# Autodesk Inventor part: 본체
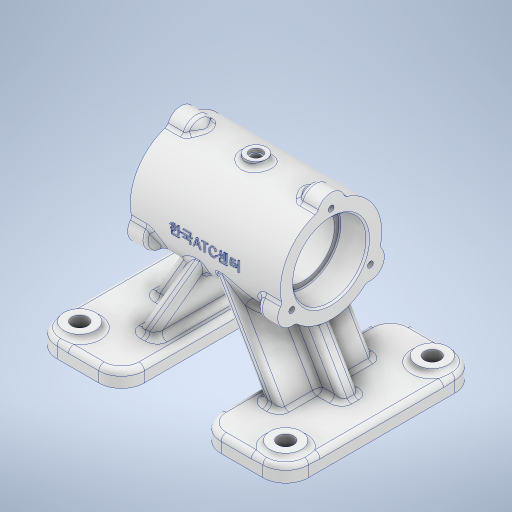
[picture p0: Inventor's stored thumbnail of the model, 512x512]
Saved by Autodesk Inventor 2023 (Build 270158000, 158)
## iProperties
Created: 2026-04
Part Number: 본체
Material: 알루미늄 6061
Document SubType Name: Modeling
Designer: 4강의실
Density: 2.7 g/cm^3
Appearance: 알루미늄 - 평지
Mass: 773.015 g
Surface Area: 685.715 cm^2
Volume: 286.302 cm^3
Author: 4강의실
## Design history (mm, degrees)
sketch "스케치1"
  geometry: L1 (-72, 55)-(72, 55); L2 (72, 55)-(72, -55); L3 (72, -55)-(-72, -55); L4 (-72, -55)-(-72, 55); L5 (-72, 55)-(72, -55); L6 (72, 55)-(-72, -55); L7 (-22, 55)-(22, 55); L8 (22, 55)-(22, -55); L9 (22, -55)-(-22, -55); L10 (-22, -55)-(-22, 55); L11 (-22, 55)-(22, -55); L12 (22, 55)-(-22, -55); 5 further points
  constraints: 24 end point, 4 midpoint, 4 parallel, 2 perpendicular, 1 collinear, 1 horizontal
  dimensions: "d0" = 144 distance of L1.start L1.end; "d1" = 110 distance of L1.end L2.end; "d2" = 44 distance of L7.start L7.end; "d3" = 110 distance of L9.end L7.start
extrude "돌출1" new body sketch "스케치1" distance "d4" = 9; taper "d5" = 0 deg
fillet "모깎기1" dims "d6" = 13
sketch "스케치2"
  geometry: L1 (59, -42)-(-59, -42); L2 (-59, -42)-(-59, 42); L3 (-59, 42)-(59, 42); L4 (59, 42)-(59, -42); L5 (59, -42)-(-59, 42); L6 (-59, -42)-(59, 42); C1 r 9 at (-59, 42); C2 r 9 at (-59, -42); C3 r 9 at (59, -42); C4 r 9 at (59, 42); 1 further point
  constraints: 12 end point, 4 centre point, 4 coincident, 2 midpoint, 2 parallel, 1 horizontal, 1 perpendicular
  dimensions: "d7" = 118 distance of L1.start L1.end; "d8" = 84 distance of L1.end L2.end; "d9" = 18 diameter of C1; "d10" = 18 diameter of C2; "d11" = 18 diameter of C3; "d12" = 18 diameter of C4
extrude "돌출2" join sketch "스케치2" distance "d13" = 3; taper "d14" = 0 deg
sketch "스케치3"
  geometry: C1 r 9 at (0, 0) reference; C2 r 9 at (118, 0) reference; C3 r 9 at (118, -84) reference; C4 r 9 at (0, -84) reference; 5 further points
  constraints: 4 coincident
hole "구멍1" sketch "스케치3" at (0, 0), (118, 0), (118, -84), (0, -84) diameter "d15" = 9; stored, may be unused: countersink angle "d19" = 90 deg, drill point angle "d21" = 118 deg; dims "d16" = 12, "d17" = 4, "d18" = 2, "d20" = 14
sketch "스케치4"
  geometry: L1 (0, 0)-(72, 0); C1 r 29 at (72, 0)
  constraints: 2 end point, 1 centre point, 1 coincident, 1 horizontal
  dimensions: "d22" = 72 distance of L1.start L1.end; "d23" = 58 diameter of C1
extrude "돌출3" join sketch "스케치4" stored distance "d24" = 86; taper "d25" = 0 deg
sketch "스케치5"
  geometry: C1 r 29 at (0, 0) reference; 2 further points
  constraints: 1 coincident
hole "구멍2" sketch "스케치5" at (0, 0) diameter "d26" = 36; stored, may be unused: countersink angle "d30" = 90 deg, drill point angle "d32" = 118 deg; dims "d27" = 6, "d28" = 42, "d29" = 16, "d31" = 8
sketch "스케치6"
  geometry: C1 r 18 at (0, 0) reference; C2 r 21 at (0, 0); 1 further point
  constraints: 1 centre point, 1 coincident
  dimensions: "d33" = 42 diameter of C2
extrude "돌출4" cut sketch "스케치6" distance "d34" = 16; taper "d35" = 0 deg
sketch "스케치7" dims "d36" = 52
  geometry: L1 (0, 0)-(0, 26); C1 r 21 at (0, 0) reference; C2 r 8 at (0, 26); 4 further points
  constraints: 2 coincident, 2 end point, 1 centre point, 1 vertical, 3 other
  dimensions: "d38" = 16 diameter of C2
extrude "돌출5" join sketch "스케치7" distance "d39" = 10; taper "d40" = 0 deg
sketch "스케치8"
  geometry: L1 (-33, 99.942)-(-33, 106) reference; L2 (-33, 106)-(-24.181, 97.181); L3 (-33, 101)-(43, 101) reference; L4 (-43, 43)-(43, 43) reference; L5 (27, 90)-(-27, 90) reference; L6 (0, 90)-(0, 112.184); L7 (-33, 106)-(-33, 97.181); L8 (-33, 97.181)-(-24.181, 97.181); L9 (-43, 51)-(-43, 93) reference; L10 (-43, 72)-(0, 72); L11 (-33, 106)-(-33, 98); L12 (-33, 98)-(-20.448, 98); 3 further points
  constraints: 14 end point, 2 midpoint, 2 perpendicular, 2 point on line, 1 horizontal, 1 vertical
  dimensions: "d41" = 45 deg angle of L6 L2; "d42" = 8 distance of L1.end L11.end
revolve "회전1" sketch "스케치8" stored, may be unused: angle "d43" = 90 deg
sketch "스케치9"
  geometry: C1 r 18 at (0, 72) reference; C2 r 21 at (0, 72); 1 further point
  constraints: 1 centre point, 1 coincident
  dimensions: "d47" = 42 diameter of C2
extrude "돌출6" cut sketch "스케치9" distance "d48" = 16; taper "d49" = 0 deg
sketch "스케치10"
  geometry: C1 r 21 at (0, 72) reference; C2 r 21 at (0, 72); 1 further point
  constraints: 1 centre point, 1 coincident
  dimensions: "d50" = 42 diameter of C2
extrude "돌출7" cut sketch "스케치10" distance "d51" = 16; taper "d52" = 0 deg
sketch "스케치11" dims "d53" = 52
  geometry: L1 (0, 72)-(0, 98); C1 r 21 at (0, 72) reference; 3 further points
  constraints: 2 coincident, 2 end point, 1 vertical, 1 vertical alignment, 2 other
hole "구멍3" sketch "스케치11" at (0, 98) diameter "d54" = 3.242; stored, may be unused: countersink angle "d58" = 90 deg, drill point angle "d60" = 118 deg; dims "d55" = 8, "d56" = 42, "d57" = 16, "d59" = 10
sketch "스케치12"
  geometry: L1 (22, 0)-(22, 9) reference; L2 (22, 0)-(32, 0); L3 (35, 0)-(22, 0) reference; L4 (32, 0)-(32, 9); L5 (22, 9)-(35, 9) reference; L6 (32, 9)-(12.37, 43); L7 (-43, 43)-(43, 43) reference; L8 (0, 0)-(0, 43); L9 (19.298, 47)-(41.238, 9); L10 (40, -8)-(22, -8); L11 (35, 9)-(59, 9) reference; L12 (22, 9)-(35, 9) reference; L13 (-43, 43)-(43, 43) reference; L14 (0, 43)-(0, 64.426); L15 (0, 64.426)-(12.37, 43); L16 (0, 64.426)-(0, 80.426); L17 (0, 80.426)-(21.608, 43); 1 further point
  constraints: 20 end point, 8 point on line, 2 vertical, 1 collinear, 1 perpendicular
  dimensions: "d64" = 10 distance of L1.start L2.end; "d65" = 30 deg angle of L8 L6; "d66" = 8 distance between parallel lines of L6 L9
extrude "돌출8" join sketch "스케치12" stored distance "d67" = 54; taper "d68" = 0 deg
sketch "스케치13"
  geometry: L1 (10.975, 61.417)-(41.238, 9) reference; L2 (35.464, 43)-(55.094, 9); L3 (59, 9)-(35, 9) reference; L4 (-43, 43)-(43, 43) reference; 1 further point
  constraints: 2 end point, 2 point on line, 1 parallel
  dimensions: "d69" = 12 distance between parallel lines of L1 L2
feature "리브1" sketch "스케치13" dims "d70" = 1, "d71" = 10, "d72" = 0, "d73" = 0, "d74" = 1, "d75" = 1
fillet "모깎기2" dims "d76" = 3
fillet "모깎기3" dims "d77" = 3
fillet "모깎기4" dims "d78" = 3
fillet "모깎기6" dims "d80" = 3
fillet "모깎기7" dims "d81" = 3
node "작업 평면1"
sketch "스케치17"
  geometry: C1 r 6 at (0, 0); 1 further point
  constraints: 1 centre point, 1 coincident
  dimensions: "d86" = 12 diameter of C1
extrude "돌출10" join sketch "스케치17" stored distance "d87" = 10; taper "d88" = 0 deg
sketch "스케치18"
  geometry: C1 r 3.5 at (0, 0); 1 further point
  constraints: 1 centre point, 1 coincident
  dimensions: "d89" = 7 diameter of C1
extrude "돌출11" cut sketch "스케치18" distance "d90" = 2; taper "d91" = 0 deg
sketch "스케치19"
  geometry: 2 further points
  constraints: 1 coincident
hole "구멍4" sketch "스케치19" at (0, 0) diameter "d92" = 5.1881; stored, may be unused: countersink angle "d96" = 90 deg, drill point angle "d98" = 118 deg; dims "d93" = 12, "d94" = 4, "d95" = 2, "d97" = 16
node "작업 평면2"
fillet "모깎기8" dims "d100" = 3
fillet "모깎기9" dims "d101" = 3
fillet "모깎기10" dims "d102" = 3
fillet "모깎기11" dims "d103" = 3
fillet "모깎기12" dims "d104" = 0.6
chamfer "모따기1" distance "d105" = 1; stored, may be unused: second distance "d106" = 2, angle "d107" = 45 deg
fillet "모깎기13" dims "d108" = 3
fillet "모깎기14" dims "d109" = 3
sketch "스케치21"
  geometry: 2 further points
  constraints: 1 vertical alignment, 1 other
  dimensions: "d110" = 72 distance of point (59, 72) point (59, 0)
feature "엠보싱1" sketch "스케치21" dims "d111" = 0.5, "d112" = 0
sketch "스케치22"
  geometry: C1 r 18 at (0, 72) reference; C2 r 18 at (0, 72); 1 further point
  constraints: 1 centre point, 1 coincident
  dimensions: "d113" = 36 diameter of C2
extrude "돌출12" cut sketch "스케치22" extent not by distance; stored distance "d114" = 2; taper "d115" = 0 deg
node "솔리드1"
pattern_circular "원형 패턴1" dims angle "d45" = 360 deg
mirror "미러1"
pattern_circular "원형 패턴2" dims angle "d62" = 360 deg
mirror "미러2"
mirror "미러3"
mirror "미러4"
mirror "미러5"
feature "A9D066F2-1C7D-4E18-AEED-F7BC21143FA4" dims "d15" = 9, "d16" = 12, "d17" = 4, "d18" = 2, "d19" = 90 deg, "d20" = 14, "d21" = 118 deg
other parameters: "d82" = -104, "d99" = -72
